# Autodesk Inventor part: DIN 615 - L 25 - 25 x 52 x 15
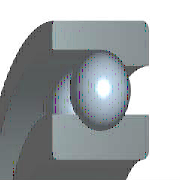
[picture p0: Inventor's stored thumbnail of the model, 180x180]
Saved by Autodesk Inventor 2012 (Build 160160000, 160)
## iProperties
Created: 2011-02
Part Number: DIN 615 - L 25 - 25 x 52 x 15
Material: Steel, Mild
Description: Magneto Ball Bearing
Document SubType Name: Modeling
Standard: DIN 615
Designer: Admin
Standards Organization: DIN
Language: en-US
Size Designation: L 25 - 25 x 52 x 15
Categories: <MemberInstance><Categories><Category DisplayName="Shaft Parts" InternalName="7f7aeb1f-a693-4053-b835-cee3144e0d98" Mnemonic="SHFT"><Category DisplayName="Beari
Density: 1 g/cm^3
IsCustomPart: 0
Author: Admin
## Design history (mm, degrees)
revolve "Body" stored, may be unused: angle "d8" = 90 deg
revolve "Ball" stored, may be unused: angle "d11" = 90 deg
pattern_circular "Balls" dims angle "d3" = 360 deg
body "Solid1"
sketch "Sketch" dims "d4" = 7.83 (= DDB)
  geometry: L1 (3.585, 19.25)-(11.415, 19.25); L2 (4.368, 16.901)-(0, 16.901); L3 (10.632, 16.901)-(15, 16.901); L4 (7.5, 23.165)-(0, 23.165); L5 (0, 26)-(15, 26); L6 (0, 12.5)-(15, 12.5); L7 (15, 12.5)-(15, 16.901); L8 (10.632, 21.599)-(15, 21.599); L9 (15, 21.599)-(15, 26); L10 (7.5, 19.25)-(7.5, 23.165); L11 (7.5, 19.25)-(7.5, 15.335); L12 (-3.2, 0)-(19.2, 0) reference; L13 (0, -2.6)-(0, 17.35) reference
  constraints: 22 end point, 5 parallel, 4 collinear, 4 point on line, 2 perpendicular, 1 horizontal, 1 midpoint, 9 other
  dimensions: "d10" = 25 diameter of L6 L12 (= WD); "d12" = 43.198 diameter of L8 L12 (= KAD1); "d14" = 38.5 diameter of L10.start L12 (= DDA); "d15" = 52 diameter of L5 L12 (= BD); "d16" = 33.802 diameter of L2 L12 (= KID1); "d17" = 15 distance between parallel lines of L13 L7 (= KB); "d18" = 7.5 distance from line of L13 L10.start (= 0.5 x KB)
fillet "Fillet1" dims "d0" = 1 (= KR1S), "d1" = 0.6 (= KR3S)
other parameters: "WD" = 25 [user parameter; used in 2 equation terms], "BD" = 52 [user parameter; used in 2 equation terms], "KB" = 15 [user parameter; used in 2 equation terms], "KR1S" = 1 [user parameter; used in 1 equation term], "KR3S" = 0.6 [user parameter; used in 1 equation term], "KID1" = 33.802 [user parameter; used in 1 equation term], "KAD1" = 43.198 [user parameter; used in 2 equation terms], "DDA" = 38.5 [user parameter; used in 1 equation term], "DDB" = 7.83 [user parameter; used in 2 equation terms], "d5" = 0, "d6" = 0, "d7" = 0, "d9" = 0, "d19" = 0, "WR" = 12.5 (= 0.5 x WD) [user parameter], "BC" = 8650000 [user parameter], "BC0" = 1730000 [user parameter], "DBB" = 46.33 [user parameter], "BR" = 26 (= 0.5 x BD) [user parameter], "BBA" = 0 [user parameter]
